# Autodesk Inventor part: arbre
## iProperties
Author: robert
Shininess: 21.0
PropertySet Name: _Private Model Information
Compacted: True
Length Units: 11269
Angle Units: 11283
Time Units: 11279
Mass Units: 11290
Length Display Precision: 3
Angle Display Precision: 2
Created: 2001-07
Part Number: arbre
Material: Par défaut
Document SubType Name: Modélisation
Designer: robert
Control State: 0
Master: False
Checked Out: False
PropertySet Name: Design Tracking Control
Density: 0.0
Volumn: 0.0
Area: 0.0
PropertySet Name: Model Information
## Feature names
1. Révolution1 [Revolution]
2. Extrusion1
3. Extrusion2
4. Extrusion3
5. Extrusion4
6. Symétrie1 [Mirror]
7. Congé1 [Fillet]
8. Congé2 [Fillet]
9. Perçage1 [Hole]
10. Chanfrein1 [Chamfer]
11. Extrusion5
